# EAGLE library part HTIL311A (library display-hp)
LED DISPLAY 1-character dot matrix, 2 decimal points Internal TTL MSI IC with Latch, Decoder, and Driver Source: http://www.taosinc.com .. til311-e6.pdf
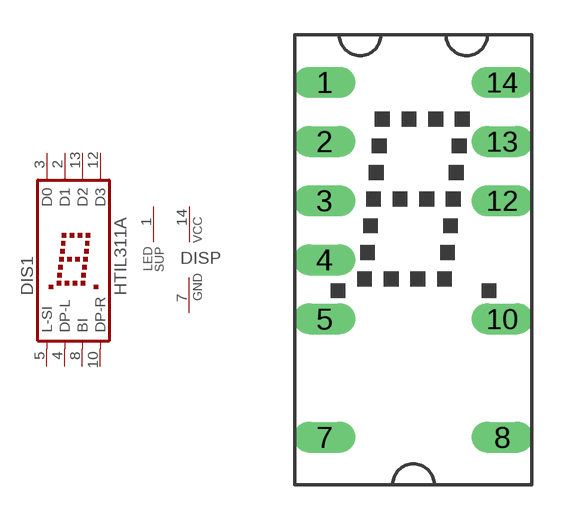
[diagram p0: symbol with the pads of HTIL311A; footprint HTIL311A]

Designator prefix DIS; gates 1=HTIL311A P=PWR

## HTIL311A (OC_FARNELL: unknown; OC_NEWARK: unknown)  [HTIL311A]
1  P:LEDSUP  in
2  1:D1  in
3  1:D0  in
4  1:DP-L  in
5  1:L-SI  in
7  P:GND  pwr
8  1:BI  in
10  1:DP-R  in
12  1:D3  in
13  1:D2  in
14  P:VCC  pwr

## Footprint HTIL311A (pad centres in mm)
LED DISPLAY 8-mm 1 character dot matrix, 2 decimal points
drill 0.813 long: 1 -3.81,7.62; 2 -3.81,5.08; 3 -3.81,2.54; 4 -3.81,0; 5 -3.81,-2.54; 7 -3.81,-7.62; 8 3.81,-7.62; 10 3.81,-2.54; 12 3.81,2.54; 13 3.81,5.08; 14 3.81,7.62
